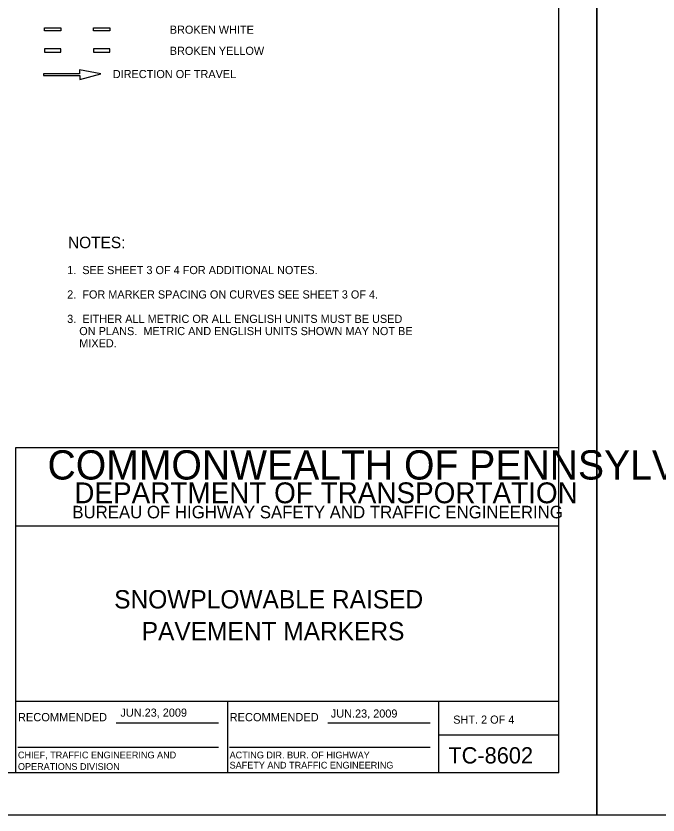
# Model space of a CAD drawing. Extents: x 639362 to 641108, y 298458 to 299646.
# Drawn here: x 639989.3 to 640225.9, y 298457.6 to 298752.3 of the extents above; entities that cross this region are included whole.
import ezdxf

# ---------------------------------------------------------------- set-up
doc = ezdxf.new("R2010")
doc.units = 0
for name, color, linetype in [('1', 7, 'Continuous'), ('2', 7, 'Continuous'), ('PLT-BNDY', 7, 'Continuous')]:
    doc.layers.add(name, color=color, linetype=linetype)

msp = doc.modelspace()

# ---------------------------------------------------------------- linework, layer by layer
at = {"layer": '1'}
for p, q in [((640189.27, 298473.19), (640189.27, 299037.19)), ((639989.27, 298473.19), (639989.27, 298593.19)), ((639989.27, 298593.19), (640189.27, 298593.19)), ((640189.27, 298564.19), (639989.27, 298564.19)), ((639989.27, 298499.57), (640189.27, 298499.57)), ((640067.27, 298499.57), (640067.27, 298473.19)), ((640145.15, 298473.19), (640145.15, 298499.57)), ((640026.24, 298491.57), (640063.87, 298491.57)), ((640104.24, 298491.57), (640141.87, 298491.57)), ((640145.15, 298487.19), (640189.27, 298487.19)), ((639989.99, 298482.68), (640063.87, 298482.68)), ((640067.99, 298482.68), (640141.87, 298482.68)), ((640189.27, 298473.19), (639403.27, 298473.19))]:
    msp.add_line(p, q, dxfattribs=at)
at = {"layer": '2'}
for p, q in [((639999.76, 298747.98), (640005.77, 298747.98)), ((640017.8, 298747.98), (640023.81, 298747.98)), ((640005.77, 298740.19), (639999.76, 298740.19)), ((640023.81, 298740.19), (640017.8, 298740.19)), ((640020.48, 298730.98), (640012.68, 298732.46)), ((640012.68, 298732.46), (640012.68, 298731.01)), ((640012.68, 298731.01), (639999.43, 298731.01)), ((639999.43, 298731.01), (639999.43, 298730.31)), ((639999.43, 298730.31), (640012.76, 298730.31)), ((640012.76, 298728.86), (640020.48, 298730.98)), ((640012.76, 298730.31), (640012.76, 298728.86))]:
    msp.add_line(p, q, dxfattribs=at)
for points in [[(640005.77, 298747.98), (640005.77, 298746.78), (639999.76, 298746.78), (639999.76, 298747.98)], [(640023.81, 298747.98), (640023.81, 298746.78), (640017.8, 298746.78), (640017.8, 298747.98)], [(639999.76, 298740.19), (639999.76, 298738.99), (640005.77, 298738.99), (640005.77, 298740.19)], [(640017.8, 298740.19), (640017.8, 298738.99), (640023.81, 298738.99), (640023.81, 298740.19)]]:
    msp.add_lwpolyline(points, dxfattribs=at)
at = {"layer": 'PLT-BNDY'}
for points in [[(639362.31, 299051.63), (640203.31, 299051.63), (640203.31, 298457.63), (639362.31, 298457.63)], [(640203.31, 299051.63), (641044.31, 299051.63), (641044.31, 298457.63), (640203.31, 298457.63)]]:
    msp.add_lwpolyline(points, close=True, dxfattribs=at)

# ---------------------------------------------------------------- texts
at = {"layer": '1'}
for s, height, p in [('COMMONWEALTH OF PENNSYLVANIA', 10.7828, (640000.9, 298581.36)), ('DEPARTMENT OF TRANSPORTATION', 7.6837, (640010.76, 298572.61)), ('BUREAU OF HIGHWAY SAFETY AND TRAFFIC ENGINEERING', 4.6253, (640010.04, 298567.04)), ('SNOWPLOWABLE RAISED', 6.75, (640025.46, 298533.81)), ('PAVEMENT MARKERS', 6.75, (640035.61, 298522.06)), ('RECOMMENDED', 3.048, (639989.99, 298492.2)), ('RECOMMENDED', 3.048, (640067.99, 298492.2)), ('SHT. 2 OF 4', 3, (640150.4, 298491.31)), ('TC-8602', 6, (640148.6, 298476.63)), ('CHIEF, TRAFFIC ENGINEERING AND', 2.5, (639989.99, 298478.51)), ('ACTING DIR. BUR. OF HIGHWAY', 2.5, (640067.99, 298478.51)), ('OPERATIONS DIVISION', 2.5, (639989.99, 298474.26)), ('SAFETY AND TRAFFIC ENGINEERING', 2.5, (640067.99, 298474.76))]:
    msp.add_text(s, height=height, dxfattribs=at).set_placement(p)
for p in [(640027.76, 298493.89), (640105.3, 298493.56)]:
    msp.add_text('JUN.23, 2009', height=3, rotation=360, dxfattribs=at).set_placement(p)
at = {"layer": '2'}
for s, height, p in [('BROKEN WHITE', 3, (640045.95, 298745.77)), ('BROKEN YELLOW', 3, (640045.95, 298737.98)), ('DIRECTION OF TRAVEL', 3, (640024.95, 298729.41)), ('NOTES:', 4.25, (640008.44, 298666.67)), ('1.  SEE SHEET 3 OF 4 FOR ADDITIONAL NOTES.', 3, (640008.13, 298657.12)), ('2.  FOR MARKER SPACING ON CURVES SEE SHEET 3 OF 4.', 3, (640008.13, 298648.12)), ('3.  EITHER ALL METRIC OR ALL ENGLISH UNITS MUST BE USED', 3, (640008.13, 298639.12)), ('    ON PLANS.  METRIC AND ENGLISH UNITS SHOWN MAY NOT BE', 3, (640008.13, 298634.62)), ('    MIXED.', 3, (640008.13, 298630.12))]:
    msp.add_text(s, height=height, dxfattribs=at).set_placement(p)

doc.saveas('drawing.dxf')
